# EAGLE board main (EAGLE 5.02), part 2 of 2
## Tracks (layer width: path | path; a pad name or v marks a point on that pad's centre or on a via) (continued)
GND  (via drill 0.51, 0.6, 0.7, 3.2) (continued)
  pour Bottom: 75.41,20.95 84.61,11.75 84.61,11.75 93.66,20.8 84.45,30
  pour Bottom: 54.61,67.31 54.61,54.93 55.88,53.66 63.02,53.66 64.77,51.91 64.77,31.91 32.86,0 120.02,0 120.02,67.31
  pour Top: 54.61,67.31 54.61,54.93 55.88,53.66 63.02,53.66 64.77,51.91 64.77,31.91 32.86,0 120.02,0 120.02,67.31
  pour Bottom: 0,68.42 43.02,68.42 44.13,67.31 67.79,67.31 75.72,67.31 120.02,67.31 120.02,107.95 66.99,107.79 66.99,123.98 91.28,147.95 98.74,147.95 103.19,152.4 103.19,166.85 0,166.85
  pour Top: 0,68.42 43.02,68.42 44.13,67.31 120.02,67.31 120.02,107.95 98.43,107.95 91.92,107.79 83.19,107.79 66.99,107.79 66.99,113.98 66.99,116.68 66.99,123.98 69.22,126.21 71.91,128.59 91.28,147.95 98.74,147.95 103.19,152.4 103.19,166.85 0,166.85
GND_VGA  (via drill 0.51)
  Top 0.203: v87.31,129.38 90.17,129.38 90.81,130.02 100.17,130.02 100.65,130.49 108.58,130.49 X8.8 | v88.74,127.95 91.28,127.95 92.08,128.75 100.17,128.75 100.65,128.27 X8.7 | v90.01,126.68 92.55,126.68 93.34,127.48 99.85,127.48 101.36,125.97 108.51,125.97 X8.6
  Bottom 0.203: 83.76,116.3 D3.14 | 83.76,116.3 83.82,116.36 83.82,116.84 | D3.15 83.79,116.81 83.82,116.84 | D3.12 84.04,115.51 83.88,115.51 83.76,115.63 83.76,116.3 | 90.96,119.86 89.85,119.86 | 89.85,119.86 89.69,119.86 | 89.85,119.86 89.85,120.33 | D3.39 89.88,120.36 89.85,120.33 | 84.04,121.51 D3.25 | D3.1 89.63,115.63 89.53,115.73 | 89.53,115.73 89.06,115.73 89.12,115.66 D3.2 | 88.9,135.73 | 88.9,135.73 C8.2 | 88.9,135.73 90.49,135.73 90.96,135.25 D2.7 90.96,134.14 | 90.96,119.86 D3.40 | 90.96,119.86 93.5,119.86 98.11,119.86 | D3.25 84.04,121.54 | 89.85,120.33 89.85,121.44 88.11,121.44 87.15,121.44 | 84.45,121.44 84.55,121.54 | 84.45,121.44 85.57,121.44 87.15,121.44 | 84.04,121.51 84.07,121.51 84.14,121.44 84.45,121.44 | 83.82,116.84 83.82,121.28 84.04,121.51 | 87.15,121.44 87.09,121.51 | 89.85,119.86 89.85,116.05 89.53,115.73 | 108.58,135.1 108.61,135.12 X8.10 108.58,135.1 | X8.5 107.42,136.26 108.58,135.1 | v89.85,132.71 90.49,132.71 90.96,133.19 90.96,134.14 | 90.96,134.14 | C10.2 109.67,151.89 109.7,151.92 109.86,151.76 109.86,149.38 | 100.65,123.82 R11.2 | 100.65,123.82 | 98.11,119.86 | 98.11,119.86 98.9,119.06 99.85,118.11 100.65,118.11 R12.2 101.54,118.05 102.08,118.59 102.08,123.19 102.08,123.67 | 100.65,123.67 | 100.65,123.67 R11.2 | 102.08,123.67 100.65,123.67 | 111.28,124.62 110.33,123.67 102.08,123.67 | 111.28,124.62 112.24,125.57 112.55,125.89 112.48,125.96 112.48,125.97 | 111.28,124.62 | 112.24,128.27 112.22,128.26 X8.7 102.41,128.26 102.08,128.59 102.08,129.38 R9.1 101.92,129.38 | 112.23,125.97 X8.6 102.47,125.97 102.08,126.36 102.08,127.16 | 112.23,125.97 112.24,125.97 | 102.08,127.16 | 102.08,127.16 R8.1 101.92,127.16
  Bottom 0.203: 102.5,130.54 X8.8 112.21,130.54 112.24,130.57 112.47,130.57 112.55,130.65 | D3.27 85.06,126.81 85.06,127.13 v87.31,129.38 | 101.92,131.6 | 87.09,126.3 87.07,126.21 87.09,124.76 D3.31 | 88.11,124.78 D3.33 | 101.92,127.16 | 112.48,125.97 112.39,125.89 112.31,125.97 112.23,125.97 | 112.48,125.97 | 112.55,130.65 | 112.55,135.1 | 112.55,135.1 108.58,135.1 | D3.26 84.52,122.78 84.45,122.71 84.39,122.78 D3.25 | 87.09,126.3 | 87.09,126.3 v88.74,127.95 | C11.2 98.58,124.3 99.06,123.82 | 99.06,123.82 | 99.06,123.82 99.22,123.67 100.65,123.67 | 100.65,123.67 | 100.65,123.67 R11.2 | 88.11,124.78 | v90.01,126.68 88.11,124.78 | 102.5,130.54 | 102.5,130.54 101.92,131.13 102.02,131.23 R10.1 101.92,131.6 | 101.92,131.6 | 101.92,131.6
  Bottom 0.61: L3.2 110.65,154.78 110.49,154.62 C9.- 109.86,154.62 109.86,149.38 112.55,146.68 112.55,138.11 112.55,135.1 112.55,130.65 112.55,126.05 112.48,125.97
  other vias: 74.77,126.36 78.11,129.7 80.65,132.08 83.03,134.62 78.26,124.14 84.77,120.65 84.77,118.11 87.47,120.65 89.22,117.95 87.63,116.36 100.97,135.25 117.79,123.98 117.79,130.97 117.63,138.11 117.79,117.79 100.81,139.86 106.05,139.86 111.28,139.86 111.44,122.4 113.19,152.08 116.52,152.08 113.19,149.54 116.52,149.54 108.58,149.54 117.63,144.3 114.3,117.79 114.3,123.98 114.3,130.97 114.3,138.11 114.3,144.3 80.64,127.32 83.03,130.33 70.64,119.38 70.64,112.55 101.44,113.19 107.63,113.19 113.67,113.19
  pour Bottom: 83.82,121.6 83.82,115.57 89.85,115.57 89.85,121.6
  pour Top: 104.3,155.73 120.02,156.05 120.02,108.43 101.6,108.43 100.01,108.43 92.55,108.27 87.63,108.27 84.93,108.27 84.45,108.27 83.5,108.27 81.92,108.27 80.96,108.27 80.33,108.27 78.9,108.27 78.11,108.27 77.63,108.27 67.79,108.27 67.79,123.67 69.53,125.41 91.44,147 98.9,147 104.3,152.4
  pour Bottom (isolate 0.406): 104.3,155.73 120.02,156.05 120.02,108.58 67.79,108.43 67.79,123.67 91.44,147 98.9,147 104.3,152.4
HEADPHONE_L
  Bottom 0.254: 15.08,54.77 18.41,54.77 19.53,53.66 C27.- | 15.08,54.77 15.08,54.93 | 15.08,54.93 R28.2 | 15.08,54.93 | 13.02,53.65 13.02,53.66 | X11.2 13.02,53.65 | X12.L 12.6,55.19 13.02,54.77 | 13.02,53.65 13.02,53.66 13.02,54.77 | 13.02,53.65 | 13.02,54.77 15.08,54.77
HEADPHONE_R  (via drill 0.7)
  Top 0.254: X11.1 11.75,51.12 11.75,59.37 v13.02,60.64
  Bottom 0.254: 15.08,60.64 18.1,60.64 19.53,62.07 21.43,62.07 | 21.43,62.07 | 21.43,62.07 C24.- | 15.08,60.64 R27.2 15.08,60.48 | 15.08,60.64 v13.02,60.64 12.38,60.01 10.95,60.01 10.32,59.37 10.32,55.56 9.68,54.93 9.68,53.5 9.7,53.51 X12.R
IOB  (via drill 0.51)
  Top 0.203: v89.69,130.17 90.17,130.65 100.01,130.65 100.97,131.6 106.05,131.6 X8.3
  Bottom 0.203: X8.3 | 103.74,131.69 103.66,131.69 | 103.74,131.69 104.03,131.69 | 103.66,131.69 103.59,131.69 | X8.3 | D3.28 85.57,126.05 v89.69,130.17 | 103.66,131.69 103.66,131.76 | X8.3 103.74,131.69 | X8.3 | 103.74,131.6 | 103.74,131.6 R10.2 | 103.66,131.69 103.66,131.68 103.74,131.6
IOG  (via drill 0.51)
  Top 0.203: v90.96,128.9 91.44,129.38 106.05,129.38 X8.2
  Bottom 0.203: R9.2 103.66,129.38 | R9.2 103.66,129.38 | D3.32 87.6,125.54 v90.96,128.9 | R9.2 103.66,129.38 | 103.66,129.38 103.69,129.4 | X8.2 106.05,129.38 R9.2
IOR  (via drill 0.51)
  Top 0.203: v92.23,127.63 92.55,127.95 92.71,128.11 100.01,128.11 100.97,127.16 106.05,127.16 X8.1
  Bottom 0.203: D3.34 88.61,123.86 89.38,124.62 v92.23,127.63 | X8.1 106.05,127.16 | 106.05,127.16 R8.2 | 106.05,127.16
LCD-B0  (via drill 0.51)
  Top 0.203: X1.17 79.38,76.83 84.61,81.91 84.61,104.62 | 84.61,104.62 84.58,104.65 | v81.44,111.6 81.44,110.65 84.6,107.49 X7.20 84.6,104.63 84.61,104.62
  Bottom 0.203: v81.44,111.6 81.44,116.84 81.92,117.32 D3.16
LCD-B1  (via drill 0.51)
  Top 0.203: X1.18 | X1.18 78.26,71.12 | 78.26,71.12 | 78.26,71.12 78.11,71.28 78.11,76.52 83.82,81.91 | 83.82,81.91 | 83.82,81.91 84.1,82.2 X7.19 | v80.64,112.55 80.64,110.81 84.1,107.35 X7.19 | X7.19 84.14,104.7
  Bottom 0.203: D3.17 81.15,117.82 80.64,117.32 v80.64,112.55
LCD-B2  (via drill 0.51)
  Top 0.203: X1.19 76.83,76.04 83.6,82.49 X7.18 83.6,107.22 79.85,110.97 v79.85,113.51
  Bottom 0.203: D3.18 80.39,118.33 79.85,117.79 v79.85,113.51
LCD-B3  (via drill 0.51)
  Top 0.203: X1.20 75.56,71.28 75.56,75.56 82.95,82.63 83.1,82.79 X7.17 83.1,107.08 79.06,111.12 v79.06,114.46
  Bottom 0.203: D3.19 79.63,118.84 79.06,118.27 v79.06,114.46
LCD-B4  (via drill 0.51)
  Top 0.203: 82.55,83.03 74.3,75.09 X1.21 | 82.55,83.03 82.42,82.89 | 82.55,83.03 82.6,83.08 X7.16 82.6,106.95 78.26,111.28 v78.26,115.41
  Bottom 0.203: D3.20 78.87,119.35 78.26,118.74 v78.26,115.41
LCD-B5  (via drill 0.51)
  Top 0.203: X1.22 74.14,70.17 73.03,71.28 73.03,74.61 81.92,83.19 | 81.92,83.19 81.92,83.18 | 81.92,83.19 | 81.92,83.19 82.1,83.37 X7.15 82.1,106.81 77.47,111.44 v77.47,116.36
  Bottom 0.203: v77.47,116.36 77.47,119.22 78.11,119.86 D3.21
LCD-B6  (via drill 0.51)
  Top 0.203: X1.23 71.75,74.14 81.6,83.66 X7.14 81.6,106.68 76.68,111.6 v76.68,117.32
  Bottom 0.203: D3.22 77.34,120.36 76.68,119.7 v76.68,117.32
LCD-B7  (via drill 0.51)
  Top 0.203: X1.24 70.48,71.28 70.48,73.66 80.44,83.3 | v75.88,118.27 75.88,111.76 81.1,106.54 X7.13 81.1,84 81.12,83.98 80.44,83.3 | 80.44,83.3
  Bottom 0.203: D3.23 76.58,120.87 75.88,120.17 v75.88,118.27
LCD-DVAL  (via drill 0.51)
  Top 0.203: v76.52,107.95 | v76.52,107.95 74.45,105.89 74.45,88.74 v72.55,86.84 | v72.55,86.84 | X1.25 69.22,73.34 | 69.22,73.34 | v78.9,84.77 78.9,83.66 78.9,83.34 69.22,73.66 69.22,73.34
  Bottom 0.203: D3.11 84.55,113.76 83.82,113.03 83.82,111.76 80.64,108.58 | 80.64,108.58 | 80.49,108.43 80.64,108.58 | 80.49,108.43 | 80.49,108.43 80.33,108.27 76.83,108.27 v76.52,107.95 | v78.9,84.77 74.61,84.77 v72.55,86.84 | v72.55,86.84
LCD-G0  (via drill 0.51)
  Top 0.203: X1.9 89.53,77.95 88.58,78.9 88.58,104.46 | 88.58,104.46 | v90.33,109.85 88.6,108.13 X7.28 88.6,104.63 88.58,104.62 88.58,104.46
  Bottom 0.203: v90.33,109.85 90.33,110.49 89.38,111.44 89.38,112.87 88.61,113.63 D3.3
LCD-G1  (via drill 0.51)
  Top 0.203: X1.10 88.27,71.28 88.27,78.42 88.11,78.58 88.11,104.62 | v89.22,110.33 88.1,109.21 X7.27 88.1,104.62 88.11,104.62 | 88.11,104.62 88.08,104.64
  Bottom 0.203: v89.22,110.33 88.9,110.65 88.9,112.71 88.11,113.51 D3.4
LCD-G2  (via drill 0.51)
  Top 0.203: X1.11 87,79.53 87.39,79.93 | 87.39,79.93 87.42,79.96 | 87.39,79.93 87.6,80.14 X7.26 87.6,110.46 v88.11,110.97 | v88.11,110.97
  Bottom 0.203: v88.11,110.97 88.42,111.28 88.42,112.55 87.6,113.38 D3.5
LCD-G3  (via drill 0.51)
  Top 0.203: 85.72,79.06 86.84,80.17 | 86.84,80.17 86.92,80.25 | 85.72,79.06 | 85.72,79.06 85.72,71.28 X1.12 | 86.84,80.17 87,80.33 87.1,80.43 X7.25 87.1,111.55 v87.63,112.08
  Bottom 0.203: v87.63,112.08 | v87.63,112.08 87.63,112.71 87.09,113.25 D3.6
LCD-G4  (via drill 0.51)
  Top 0.203: X1.13 84.45,78.58 86.36,80.49 | 86.36,80.49 86.44,80.57 86.42,80.59 | 86.36,80.49 86.6,80.73 X7.24 86.6,111.52 v86.04,112.08
  Bottom 0.203: D3.7 86.58,113.25 86.04,112.71 v86.04,112.08
LCD-G5  (via drill 0.51)
  Top 0.203: X1.14 83.19,71.28 83.19,78.1 86.1,81.02 X7.23 86.1,110.43 v85.57,110.97
  Bottom 0.203: v85.57,110.97 85.25,111.28 85.25,112.55 86.07,113.38 D3.8
LCD-G6  (via drill 0.51)
  Top 0.203: X1.15 81.92,77.63 85.6,81.31 X7.22 85.6,109.34 v84.45,110.33
  Bottom 0.203: D3.9 85.57,113.51 84.77,112.71 84.77,110.65 v84.45,110.33
LCD-G7  (via drill 0.51)
  Top 0.203: X1.16 80.64,71.28 80.64,77.15 85.1,81.61 X7.21 85.1,108.1 v83.34,109.85
  Bottom 0.203: D3.10 85.06,113.63 84.3,112.87 84.3,111.44 83.34,110.49 v83.34,109.85
LCD-HSYNC  (via drill 0.51)
  Top 0.203: X1.27 66.67,78.26 79.06,90.65 79.06,100.01 78.11,100.96 78.11,101.92 79.06,102.87 79.06,104.62 79.08,104.64 79.12,104.64 | v74.3,120.17 74.3,112.08 79.1,107.27 X7.9 | 79.12,104.64 X7.9 | X7.9 | 79.12,104.64 79.14,104.62
  Bottom 0.203: v74.3,120.17 74.3,120.65 74.3,121.13 75.41,122.24 81.28,122.24 83.98,124.94 83.98,127.79 87.15,130.97 94.61,130.97 96.04,132.4 96.04,133.67 | 96.04,133.67 D2.3 | 96.04,133.67
LCD-PCLK  (via drill 0.51)
  Top 0.203: v75.09,119.22 75.09,111.92 80.1,106.91 X7.11 80.1,104.63 80.08,104.6 80.08,102.54 79.3,101.76 79.3,101.04 80.09,100.25 80.08,87.54 80.08,87.38 80.01,87.31 v70.17,77.47
  Bottom 0.203: v75.09,119.22 75.09,120.65 75.82,121.38 D3.24 | R1.2 69.11,76.57 v70.17,77.47
LCD-R0  (via drill 0.51)
  Top 0.203: X1.1 99.69,74.29 92.71,81.12 | 92.71,81.12 | 92.71,81.12 92.6,81.23 X7.36 92.6,106.57 97.79,111.76 v97.79,118.27
  Bottom 0.203: 97.79,118.59 v97.79,118.27 97.79,118.74 97.19,119.35 D3.41
LCD-R1  (via drill 0.51)
  Top 0.203: X1.2 98.42,71.28 98.42,74.61 92.1,80.94 X7.35 92.1,106.71 97,111.6 v97,117.47
  Bottom 0.203: 97,117.63 97,117.79 | D3.42 96.42,118.84 97,118.27 97,117.63 | v97,117.47 97,117.63
LCD-R2  (via drill 0.51)
  Top 0.203: X1.3 97.16,75.09 91.6,80.64 91.6,80.65 X7.34 91.6,106.84 95.89,111.12 | 95.89,111.12 | 95.89,111.12 96.04,111.28 | 96.04,111.28 | 96.04,111.28 96.2,111.44 v96.2,116.36
  Bottom 0.203: D3.43 95.82,118.33 96.2,117.95 v96.2,116.36
LCD-R3  (via drill 0.51)
  Top 0.203: X1.4 95.89,71.28 95.89,75.56 91.1,80.35 X7.33 91.1,106.98 95.41,111.28 v95.41,115.41
  Bottom 0.203: D3.44 94.9,117.82 95.41,117.32 v95.41,115.41
LCD-R4  (via drill 0.51)
  Top 0.203: X1.5 94.61,76.04 90.65,80.01 | 90.65,80.01 | 90.65,80.01 90.6,80.06 X7.32 90.6,107.11 94.61,111.12 v94.61,114.46
  Bottom 0.203: D3.45 94.14,117.32 94.61,116.84 v94.61,114.46
LCD-R5  (via drill 0.51)
  Top 0.203: X1.6 93.34,71.28 93.34,76.52 90.17,79.69 | 90.17,79.69 | 90.17,79.69 90.1,79.76 X7.31 90.1,107.25 93.66,110.81 93.82,110.97 v93.82,113.51
  Bottom 0.203: D3.46 93.38,116.81 93.82,116.36 v93.82,113.51
LCD-R6  (via drill 0.51)
  Top 0.203: 89.69,79.37 92.08,76.99 X1.7 | 89.69,79.37 | 89.69,79.37 89.6,79.47 X7.30 89.6,107.38 93.03,110.81 v93.03,112.55
  Bottom 0.203: D3.47 92.46,116.3 93.03,115.73 v93.03,112.55
LCD-R7  (via drill 0.51)
  Top 0.203: X1.8 90.81,71.28 90.81,77.47 89.1,79.17 X7.29 89.1,107.52 92.23,110.65 v92.23,111.6
  Bottom 0.203: D3.48 91.69,115.79 92.23,115.25 v92.23,111.6
LCD-VSYNC  (via drill 0.51)
  Top 0.203: X1.29 64.14,76.99 78.58,91.44 78.58,99.85 77.47,100.96 77.47,101.92 78.58,103.03 78.58,104.62 | 78.58,104.62 | v73.5,121.13 73.5,112.24 78.6,107.14 X7.8 78.6,104.64 78.58,104.62
  Bottom 0.203: v73.5,121.13 73.5,121.6 74.77,122.87 81.12,122.87 83.34,125.09 83.34,128.11 87.47,132.24 87.47,136.84 87.79,137.16 90.01,137.16 91.12,138.27 94.14,138.27 94.77,138.91 94.77,140.02 | 94.77,140.02 | 94.77,140.02 D2.11
LINE_IN_L  (via drill 0.7)
  Top 0.254: X13.2 31.59,25.72 29.53,27.78 17.62,27.78 v15.56,29.84
  Bottom 0.254: R39.2 16.03,32.07 15.56,31.59 | v15.56,29.84 | 15.56,31.59 v15.56,29.84 | X15.L 15.56,31.11 15.56,31.59
LINE_IN_R  (via drill 0.7)
  Top 0.254: X13.1 33.02,24.45 33.02,26.35 30.64,28.73 21.59,28.73 v13.65,36.67
  Bottom 0.254: R34.2 14.76,37.78 13.89,36.91 | v13.65,36.67 13.89,36.91 | 13.89,36.91 13.97,36.99 13.81,36.83 v13.65,36.67 | v13.65,36.67 13.65,34.29 12.86,33.5 10.95,33.5 10,32.54 10,27.3 9.68,26.99 9.7,26.97 X15.R
LINE_OUT_L  (via drill 0.7)
  Top 0.254: X11.6 19.68,50.8 19.68,44.93 v18.1,43.34
  Bottom 0.254: 15.88,41.59 R26.2 15.93,41.69 16.03,41.59 C23.2 18.1,41.59 v18.1,43.34
  Bottom 0.305: 15.88,41.59 14.05,41.59 12.62,43.02 12.62,44.37 12.7,44.45 | 12.7,44.45 | 12.7,44.45 X10.L
LINE_OUT_R
  Bottom 0.254: 17.94,47.62 | 17.94,47.62 C16.2 18.1,47.62 X11.5 | 17.94,47.62 17.84,47.52 R25.2 15.82,47.52 15.72,47.62 12.7,47.62 | 12.7,47.62 | 12.7,47.62 11.75,46.67 10.32,46.67 9.68,46.04 9.68,40.16 9.7,40.18 X10.R
MIC1
  Bottom 0.254: C34.1 18.73,17.62 19.21,18.1 22.86,18.1 23.65,17.3 27.46,17.3 29.37,19.21 29.37,26.83 30.8,28.26 37.47,28.26 39.21,30 39.21,31.27 38.42,32.07 D7.21
MIC1_IN  (via drill 0.7)
  Top 0.254: X14.5 | X14.5 11.75,24.45 11.75,16.03 v13.02,14.76
  Bottom 0.254: X16.L 12.6,15.18 v13.02,14.76
  Bottom 0.61: X16.L 12.7,17.78 12.86,17.62 C34.2
MIC1_SUP
  Bottom 0.254: R36.1 14.13,19.68 13.65,20.16 13.02,20.16 | 13.02,20.16 11.27,20.16 10.48,19.37 10.48,16.35 9.68,15.56 9.68,13.65 9.7,13.64 X16.R | X14.6 13.02,20.16
MIC2
  Bottom 0.254: C44.1 22.6,26.88 24.61,28.89 37.31,28.89 38.58,30.16 38.58,31.11 37.91,31.78 D7.22
MIC2_IN
  Bottom 0.254: 20.95,25.72 C44.2 | X14.1 20.95,25.72 | 20.95,25.72
MIC2_SUP
  Bottom 0.254: R41.1 20.95,23.18 X14.2
N$1
  Bottom 0.203: D2.10 93.5,141.6 93.66,141.76 97.16,141.76 97.31,141.6 97.31,140.02 | 97.31,140.02 | 97.31,140.02 D2.13
N$2
  Bottom 0.203: D2.4 94.77,135.1 95.25,135.57 98.11,135.57 98.58,135.1 98.58,133.98 | 98.58,133.98 | 98.58,133.98 D2.1
N$3  (via drill 0.76)
  Top 0.203: 115.25,45.08 v115.73,45.08 115.25,45.08 | 115.25,45.08 115.09,45.08 | X21.P$8 113.02,44.43 113.67,45.08 115.25,45.08
  Bottom 0.203: v115.73,45.08 R52.2 | v115.73,45.08
N$4
  Bottom 0.203: D8.CTS 4.13,79.53 5.24,80.64 5.24,90.96 3.97,92.23 D8.RTS
N$5
  Bottom 0.203: 40.32,135.57 | R21.2 40.32,135.57 | D5.9 40.96,136.21 40.32,135.57
N$6  (via drill 0.76)
  Top 0.203: v104.14,90.8 104.14,82.23 103.82,81.91 v103.82,79.22 | v103.82,79.22
  Bottom 0.203: 112.24,82.07 D1.6 112.37,82.05 112.24,81.91 112.08,82.07 111.12,82.07 110.17,81.12 107.31,78.26 104.78,78.26 v103.82,79.22 103.82,79.37 | V3.1 109.38,89.7 108.9,90.17 107.63,90.17 107,90.8 v104.14,90.8 | 103.82,79.37 R5.1 103.82,81.12 103.66,81.28 | 103.82,79.37 v103.82,79.22
N$7
  Bottom 0.203: D3.36 89.63,123.13 89.85,123.35 91.76,123.35 92.23,123.82 96.04,123.82 96.52,124.3 96.52,125.25 C13.2
N$8
  Bottom 0.203: D3.35 89.12,123.57 89.38,123.82 90.81,123.82 91.44,123.82 92.87,125.25 94.46,125.25 | 94.46,125.25 | 94.46,125.25 C12.2
N$9
  Bottom 0.508: V3.3 108.43,95.57 108.27,95.73 108.11,95.73 | L1.P$2 106.68,95.73 108.11,95.73 | V2.A 108.13,95.75 108.11,95.73
N$10
  Bottom 0.203: 113.82,89.75 R6.1 | 113.82,89.75 113.93,89.75 | D1.3 106.19,82.06 106.2,82.07 108.11,82.07 108.27,82.23 109.22,83.18 109.22,85.41 110.33,86.52 113.82,86.52 116.2,86.52 116.68,86.99 116.68,89.53 116.52,89.69 113.82,89.69 113.82,89.75
  Bottom 0.508: 113.19,91.92 R4.2 | R6.1 113.19,91.92 | 113.19,91.92
N$11
  Bottom 0.203: D3.37 91.85,121.38 | 91.85,121.38 | 91.85,121.38 | 100.65,122.08 R11.1 | 100.65,122.08 100.65,121.76 100.65,121.6 100.17,121.13 93.34,121.13 92.71,121.76 92.23,121.76 91.85,121.38 | 100.65,122.08 100.49,121.92 | 91.85,121.38
N$12
  Bottom 0.254: D7.3 46.09,39.56 46.16,39.58 47.31,40.72 | 47.31,40.72 | 47.31,40.72 50.88,40.72 | 50.88,40.72 | 50.88,40.72 51.44,40.16 53.98,40.16 54.13,40 54.13,38.1 | 54.13,36.99 54.2,36.92 B2.2 | 57.63,38.1 | 57.63,38.1 C38.1 | B2.2 57.56,38.04 57.63,38.1 | 54.13,38.1 | 54.13,38.1 B2.2
N$13
  Bottom 0.254: D7.2 45.78,40.07 46.91,41.2 50.88,41.2 51.44,41.75 51.44,46.51 52.55,47.62 54.13,47.62 54.2,47.69 B2.1 57.4,47.69 57.57,47.52 C37.1
N$15
  Bottom 1.016: X4.2 101.12,77.79 101.12,80.96 | 101.12,80.96 | 101.12,80.96 V1.A | 101.12,80.96
N$16
  Bottom 0.254: R32.1 C32.2 43.55,28.04 43.18,28.42 R31.1
N$17
  Bottom 0.254: 40.48,25.72 C31.2 | 40.48,25.72 | 40.48,25.72 | R29.1 40.48,25.72 | R30.1 40.54,25.77 40.48,25.72
N$18
  Bottom 0.254: D7.36 33.24,40.58 31.27,42.54 31.27,43.66 29.05,45.88 25.4,45.88 23.76,47.52 C21.2 19.95,47.52 19.84,47.62 | 19.84,47.62 | C16.1 19.84,47.62
N$19
  Bottom 0.254: D7.35 31.21,40.07 29.53,41.75 29.53,42.7 28.26,43.97 25.4,43.97 23.12,41.69 C22.2 21.91,41.59 C23.1
N$20
  Bottom 0.254: D7.41 38.93,45.53 36.83,47.62 34.61,47.62 32.86,49.37 32.86,59.85 30.64,62.07 29.53,62.07 C24.+
N$21
  Bottom 0.254: C27.+ 28.73,53.66 31.59,50.8 31.59,48.74 33.97,46.35 36.2,46.35 37.78,44.77 37.91,44.58 D7.39
N$22  (via drill 0.7)
  Top 0.254: v43.02,32.23 v40.01,32.23 37.94,30.16 32.7,30.16 30.96,31.91 v30.96,34.77
  Bottom 0.254: D7.28 33.02,36.51 32.38,35.88 32.38,35.08 32.07,34.77 v30.96,34.77 | v40.01,32.23 40.48,32.23 | 40.48,32.23 40.96,32.23 40.96,33.5 | 40.96,33.5 | 40.96,33.5 D7.16 | D7.17 40.45,32.26 40.48,32.23 | D7.18 39.94,32.29 v40.01,32.23 | v40.01,32.23 39.53,32.23 39.43,32.29 D7.19 | D7.20 38.93,32.26 v40.01,32.23 | D7.13 42.48,32.77 v43.02,32.23 44.61,33.81 44.61,34.92 44.55,34.99 D7.12
N$23
  Bottom 0.254: D7.15 41.47,31.62 40.96,31.11 | 40.96,31.11 | 40.96,31.11 40.48,30.64 40.48,29.69 | 40.48,29.69 | C31.1 40.48,29.69
N$24
  Bottom 0.254: C28.1 31.11,57.78 32.23,56.67 32.23,49.05 34.29,46.99 36.51,46.99 38.42,45.08 D7.40
N$25
  Bottom 0.254: D7.14 41.97,31.69 42.55,31.11 44.61,31.11 45.24,30.48 45.24,29.84 45.35,29.74 | 45.35,29.74 45.4,29.69 | C32.1 45.35,29.74
N$26
  Bottom 0.254: R40.1 27.78,25.24 27.62,25.08 27.15,25.08 25.24,23.18 C45.+ 25.24,23.02 | 25.24,23.02 | R41.2 25.08,23.18 25.24,23.02
N$27
  Bottom 0.254: 22.7,32.07 C35.2 | 20.48,32.07 22.7,32.07 | R39.1 20.48,32.07 | 22.7,32.07 | 20.48,32.07 | 20.48,32.07 R38.1 | 20.48,32.07
N$28
  Bottom 0.254: 18.26,37.78 R34.1 20.48,37.78 | 20.48,37.78 C33.2 | 20.48,37.78 R37.1
N$29
  Bottom 0.254: R36.2 20.95,19.68 C36.+ 23.77,19.72 23.81,19.68 R35.1
N$30
  Bottom 0.254: 24.29,37.78 C33.1 24.92,37.78 25.72,36.99 25.72,31.59 27.15,30.16 36.99,30.16 37.31,30.48 37.31,30.8 36.89,31.21 D7.24
N$31
  Bottom 0.254: C35.1 24.61,32.07 24.61,31.75 26.83,29.53 37.15,29.53 37.78,30.16 37.78,31.11 37.4,31.5 D7.23
N$32
  Bottom 0.254: C40.1 29.79,33.08 29.84,33.02 C41.1 31.69,33.08 31.75,33.02 31.81,33.08 C39.1 32.6,33.08 33.02,33.5 33.02,35.56 33.46,36 D7.27
N$33
  Bottom 0.254: D7.30 32.48,37.53 31.59,38.42 31.11,38.42 C42.2
N$34
  Bottom 0.254: D7.29 32.42,37.02 31.75,36.35 C43.2 30.96,36.35
N$35  (via drill 0.7)
  Top 0.254: v63.02,50.16 v58.26,50.16
  Bottom 0.203: 13.34,8.57 13.18,8.57 11.91,7.3 10.32,7.3 9.53,6.51 9.53,5.24 11.07,3.69 | 11.07,3.69 11.11,3.65 | B1.3 11.07,3.69
  Bottom 0.254: D7.48 42.48,42.48 43.5,43.5 | 43.5,43.5 | 43.5,43.5 50.64,50.64 57.78,50.64 v58.26,50.16 | 63.02,50.01 v63.02,50.16 | 63.02,50.01 | 63.02,50.01 62.55,49.53 62.55,34.29 62.55,33.81 59.05,30.32 58.74,30.32 48.58,30.32 47.94,29.69 47.94,22.7 45.09,19.84 34.45,19.84 23.18,8.57 13.34,8.57
N$36  (via drill 0.76)
  Top 0.203: 115.25,34.92 v115.73,34.92 115.25,34.92 | X21.P$12 109.27,40.43 110.17,39.53 114.78,34.92 115.25,34.92
  Bottom 0.203: v115.73,34.92 R46.2 | v115.73,34.92
N$37  (via drill 0.76)
  Top 0.203: v115.73,37.46 115.09,37.46 114.78,37.46 110.81,41.43 X21.P$11
  Bottom 0.203: v115.73,37.46 R47.2 | v115.73,37.46
N$38  (via drill 0.76)
  Top 0.203: v115.73,40 115.09,40 114.78,40 112.35,42.43 X21.P$10
  Bottom 0.203: v115.73,40 R49.2 | v115.73,40
N$39  (via drill 0.76)
  Top 0.203: v115.73,50.16 115.09,50.16 114.94,50.16 111.2,46.43 X21.P$6
  Bottom 0.203: v115.73,50.16 R50.2 | v115.73,50.16
N$40
  Bottom 0.203: D10.31 95.27,42.68 99.54,38.42 99.54,36.35 100.81,35.08 106.05,35.08 106.52,35.56 106.52,36.35 106.39,36.38 | 106.39,36.38 106.52,36.51 | 106.39,36.38 C52.1
N$41
  Bottom 0.203: D10.28 96.77,43.09 99.22,40.64 | 99.22,40.64 | 99.22,40.64 99.54,40.32 106.2,40.32 106.52,40 106.52,39.21 106.52,39.37 C52.2 106.52,38.34 106.84,38.02 110.25,38.02 110.81,37.46 R47.1
N$42
  Bottom 0.203: D10.30 95.77,42.82 100.01,38.58 100.01,37.15 100.81,36.35 103.82,36.35 103.85,36.38 C51.1
N$43
  Bottom 0.203: 96.36,42.86 96.28,42.94 | 96.36,42.86 100.04,39.18 C51.2 104.3,38.02 104.78,37.54 109.78,37.54 110.33,36.99 110.33,35.48 110.89,34.92 R46.1 | D10.29 96.27,42.95 96.36,42.86
N$44
  Bottom 0.203: D10.32 94.77,42.55 99.06,38.26 99.06,36.19 100.65,34.61 107.95,34.61 108.74,35.4 108.74,36.19 C53.1
N$45
  Bottom 0.203: D10.27 97.27,43.22 99.69,40.8 107.95,40.8 108.74,40 | 108.74,40 R49.1 | C53.2 108.74,40
N$46
  Bottom 0.203: D10.17 99.86,48.26 101.28,49.69 103.98,49.69 104.11,49.82 C54.1
N$47
  Bottom 0.203: D10.18 102.25,47.76 103.03,46.99 104.14,46.99 | 104.14,46.99 | 104.14,46.99 C54.2 104.3,48.26 104.69,48.66 109.78,48.66 111.28,50.16 111.92,50.16 | 111.92,50.16 | 111.92,50.16 R50.1
N$48
  Bottom 0.203: D10.16 98.27,49.37 99.85,50.96 106.05,50.96 106.52,50.48 106.52,49.85 106.36,49.85 C56.1
N$49
  Bottom 0.203: D10.19 101.48,47.26 103.03,45.72 105.89,45.72 106.52,46.35 | 106.36,46.83 | 106.36,46.83 C56.2 | 106.52,46.35 106.36,46.83 | 106.52,46.35 106.52,47.78 106.92,48.18 109.78,48.18 110.49,47.47 111.6,47.47 111.76,47.62 R51.1
N$50
  Bottom 0.203: D10.15 97.77,49.51 99.69,51.43 | 99.69,51.43 99.54,51.28 99.69,51.43 | 99.69,51.43 108.27,51.43 108.74,50.96 C57.1
N$51
  Bottom 0.203: D10.20 101.19,46.76 101.92,46.04 102.71,45.24 108.74,45.24 | 108.74,45.24 108.74,46.35 C57.2 | R52.1 111.92,45.08 111.76,45.24 108.74,45.24
N$52
  Bottom 0.203: D10.14 97.27,49.64 100.33,52.7 105.73,52.7 | 105.73,52.7 | 105.73,52.7 C58.1
N$53
  Bottom 0.203: D10.13 96.77,49.78 100.97,53.97 108.27,53.97 108.74,53.5 108.74,52.7 C58.2 112.24,52.7 | 112.24,52.7 R53.1 | 112.24,52.7
N$54
  Bottom 0.203: D10.9 94.77,50.32 100.33,55.88 100.33,57.94 101.28,58.9 103.98,58.9 | 103.98,58.9 | 103.98,58.9 C59.1
N$55
  Bottom 0.203: D10.10 95.27,50.18 101.12,56.04 103.82,56.04 103.85,56.07 C59.2 104.3,57.31 104.7,57.71 109.86,57.71 110.41,58.26 110.41,59.69 111.05,60.32 111.68,60.32 111.76,60.25 111.84,60.32 R56.1
N$56
  Bottom 0.203: D10.8 93.66,48.26 93.34,48.58 93.34,49.53 99.85,56.04 99.85,59.37 100.81,60.32 106.05,60.32 106.52,59.85 106.52,58.9 C60.1
N$57
  Bottom 0.203: D10.11 95.77,49.96 95.89,50.16 100.65,54.93 106.05,54.93 106.52,55.4 C60.2 106.52,56.83 106.92,57.23 110.57,57.23 111.12,57.78 R57.1
N$58
  Bottom 0.203: D10.7 93.52,47.76 92.87,48.42 92.87,49.69 99.38,56.2 99.38,59.53 100.65,60.8 107.95,60.8 108.74,60.17 108.74,58.9 108.58,58.9 C61.1
N$59
  Bottom 0.203: D10.12 96.27,49.91 100.81,54.45 107.79,54.45 108.74,55.24 108.74,56.04 | 108.74,56.04 | 108.74,56.04 C61.2 110.14,56.07 110.97,55.24 R58.1
N$60
  Bottom 0.203: R48.2 91.12,43.82 91.12,43.81 | D10.1 93.02,44.76 92.08,43.81 91.12,43.81 | 91.12,43.81 | 91.12,43.81 C55.1
N$61
  Bottom 0.203: D10.4 93.44,46.26 92.87,46.83 91.92,47.78 91.92,49.21 91.44,49.69 R45.2 | R48.1 87.63,48.58 88.74,49.69 R45.2 | R45.2 | R45.2 | R45.2
N$62  (via drill 0.76)
  Top 0.203: v115.73,47.62 115.09,47.62 114.46,47.62 112.27,45.43 X21.P$7
  Bottom 0.203: v115.73,47.62 R51.2 | v115.73,47.62
N$63
  Bottom 0.203: R20.2 32.07,151.13 32.07,150.18 D5.1 32.07,148.27
N$64  (via drill 0.76)
  Top 0.203: v115.73,52.7 114.94,52.7 114.78,52.7 113.82,51.75 113.82,50.48 110.78,47.43 X21.P$5
  Bottom 0.203: v115.73,52.7 R53.2 | v115.73,52.7
N$65  (via drill 0.76)
  Top 0.203: v115.73,60.32 112.08,60.32 110.97,59.21 110.97,59.05 110.97,51.75 109.65,50.43 X21.P$2
  Bottom 0.203: 113.67,60.32 | 113.67,60.32 R56.2 v115.73,60.32 | v115.73,60.32
N$66  (via drill 0.76)
  Top 0.203: v115.73,57.78 115.09,57.78 113.51,57.78 | 113.51,57.78 113.82,57.78 | X21.P$3 110.24,49.43 111.92,51.12 111.92,51.28 | 113.51,57.78 111.92,56.2 111.92,51.28 | 111.92,51.28 | 111.92,51.28
  Bottom 0.203: R57.2 113.51,57.78 v115.73,57.78 | v115.73,57.78
N$67  (via drill 0.76)
  Top 0.203: v115.73,55.24 114.94,55.24 114.78,55.24 113.82,55.24 113.03,54.45 113.03,50.8 110.67,48.43 X21.P$4
  Bottom 0.203: v115.73,55.24 R58.2 | v115.73,55.24
N$68
  Bottom 0.203: R18.2 52.55,135.57 53.18,136.21 53.18,138.43 53.34,138.59 53.32,138.61 D4.9
N$69
  Bottom 0.203: R17.2 44.45,151.13 44.29,150.97 D4.1
N$70
  Bottom 0.203: D6.P$2 17.19,151.08 15.24,153.03 15.24,155.26 17.46,157.48 26.67,157.48 27.46,156.69 27.46,156.37 R22.1
N$71
  Bottom 0.203: D6.P$5 16.8,149.88 13.81,152.88 13.81,156.37 16.51,159.07 30.48,159.07 32.54,157 R24.1
N$72
  Bottom 0.203: D6.P$3 16.8,150.68 14.45,153.03 14.45,155.73 16.99,158.27 28.73,158.27 30,157 R23.1
N$73
  Bottom 0.203: D1.1 107.63,79.53 110.49,82.39 110.49,83.82 111.44,84.77 113.51,84.77 115.73,82.55 116.36,81.91 X6.2 | X6.2
N$75
  Bottom 0.203: X1.28 67.94,71.28 67.94,74.77 | 67.94,74.77 | 67.94,74.77 R1.1
SD_CD
  Bottom 0.203: X9.CD 9.8,99.42 9.84,99.38 9.84,97.63 | 9.84,97.63 9.84,97.47 12.06,95.25 38.89,95.25 43.5,99.85 43.5,115.09 49.69,121.28 49.69,127 70.48,147.8 70.48,154.62 70.96,155.1 71.28,155.1 71.75,155.57 X3.23 | 9.84,97.63 R14.2 | X3.23
SDIO-CLK  (via drill 0.51)
  Top 0.203: X2.32 61.59,161.29 61.59,160.18 60.96,159.54 60.33,158.91 60.33,152.56 59.53,151.76 56.83,151.76 v30,151.76 28.89,150.65 16.99,150.65 13.34,154.3 P1.PP | P1.PP
  Bottom 0.203: D6.P$32 26.97,144.28 28.73,146.05 28.73,150.49 v30,151.76
SDIO-CMD1  (via drill 0.51, 0.6)
  Top 0.203: X2.30 62.87,160.18 62.87,151.13 61.28,149.54 39.55,149.54 | P2.PP 7.62,153.67 8.73,152.56 13.34,152.56 14.29,151.61 14.29,150.34 15.08,149.54 16.35,149.54 | 16.35,149.54 39.55,149.54 | 16.35,149.54 v16.35,149.22 | 39.55,149.54 39.55,150.63 v39.53,150.65 | v39.53,152.64 v39.53,154.46
  Bottom 0.203: D6.P$9 17.29,148.28 v16.35,149.22 | v39.53,150.65 v39.53,152.64 | v39.53,154.46 35.56,154.46 35.4,154.62 R59.2 35.4,154.78
SDIO-D4  (via drill 0.6)
  Top 0.203: 92.08,153.19 X3.8 92.08,153.19 | v16.35,145.41 16.99,146.05 84.93,146.05 92.08,153.19 | P3.PP 8.89,151.13 9.68,150.34 9.68,146.21 10.48,145.41 v16.35,145.41 | v16.35,145.41
  Bottom 0.203: D6.P$25 16.86,141.88 16.55,141.88 16.19,142.24 16.19,145.26 v16.35,145.41
SDIO-D5  (via drill 0.51)
  Top 0.203: 93.34,155.1 93.34,153.19 85.25,145.1 v25.4,145.1 24.29,143.99 9.68,143.99 7.46,146.21 P4.PP
  Top 0.254: X3.7 | 93.34,155.1 X3.7
  Bottom 0.203: 25.39,145.08 D6.P$34 | v25.4,145.1 | 25.39,145.08 | v25.4,145.1 25.39,145.08
SDIO-D6  (via drill 0.51)
  Top 0.203: v16.35,147.95 13.81,147.95 13.18,148.59 13.18,150.49 12.54,151.13 P5.PP | P5.PP | X3.10 | X3.10 89.53,153.19 84.3,147.95 v16.35,147.95 | v16.35,147.95
  Top 0.254: X3.10 | X3.10
  Bottom 0.203: D6.P$10 16.42,147.88 v16.35,147.95
SDIO-D7  (via drill 0.51)
  Top 0.203: P6.PP 11.75,148.11 P6.PP | 90.81,155.1 90.81,153.19 84.61,147 v27.15,147 12.7,147 P6.PP | P6.PP | P6.PP
  Top 0.254: X3.9 | 90.81,155.1 X3.9
  Bottom 0.203: v27.15,147 25.08,147 23.57,145.48 D6.P$35
SDIO/!SPI!  (via drill 0.51)
  Top 0.203: X2.31 60.33,162.72 60.33,160.02 59.21,158.91 55.24,158.91 54.13,157.8 v54.13,153.83
  Bottom 0.203: D6.P$49 24.09,151.08 26.67,153.51 53.82,153.51 v54.13,153.83
SPI0-CS1  (via drill 0.51)
  Top 0.203: P14.PP 16.03,140.33 20.8,135.57 54.93,135.57 | v70.48,135.57 55.24,135.57 54.93,135.57 | v54.93,137.48 54.93,135.57
  Bottom 0.203: D4.7 51.91,146.68 52.7,145.89 58.26,145.89 59.05,145.1 59.05,142.24 | 59.05,142.24 59.05,141.6 v54.93,137.48 | R16.2 59,142.5 59.05,142.24 | X2.7 90.81,162.72 89.06,162.72 88.27,161.92 88.27,155.73 88.27,152.56 71.28,135.57 v70.48,135.57
SPI0-CS2  (via drill 0.51)
  Top 0.203: v41.59,134.46 v69.37,134.46 | v41.59,134.46 41.75,134.46 | v41.59,134.46 v29.37,134.46 21.11,134.46 16.67,138.91 9.05,138.91 P15.PP | P15.PP
  Bottom 0.203: X2.8 90.81,160.18 90.81,153.19 90.01,152.4 89.06,152.4 71.12,134.46 70.17,134.46 v69.37,134.46 | D5.7 39.69,142.24 41.91,140.02 41.91,134.78 v41.59,134.46 | v29.37,134.46 R19.2 | v29.37,134.46
SPI0-MISO  (via drill 0.51)
  Top 0.203: v67.31,132.24 v42.55,132.24 21.75,132.24 18.57,135.41 9.37,135.41 P17.PP | P17.PP
  Bottom 0.203: X2.3 95.89,162.72 95.89,153.19 93.82,151.13 | 93.82,151.13 | 93.82,151.13 89.69,151.13 70.8,132.24 v67.31,132.24 | v42.55,132.24 42.55,140.33 40.96,141.92 D5.8 40.96,151.29 42.23,152.56 52.39,152.56 53.18,151.76 D4.8 | 93.82,151.13
SPI0-MOSI  (via drill 0.51)
  Top 0.203: 33.5,131.13 29.53,131.13 | 44.93,131.13 33.5,131.13 | v66.2,131.13 44.93,131.13 | 33.5,131.13 | 33.5,131.13 v33.34,131.13 | 44.93,131.13 | 44.93,131.13 v45.56,131.13 | P16.PP 19.21,133.98 22.07,131.13 29.53,131.13 | 29.53,131.13
  Bottom 0.203: X2.4 | X2.4 98.27,160.34 | 98.27,160.34 | 98.27,160.34 98.42,160.18 98.42,160.02 98.42,153.19 95.73,150.49 | 95.73,150.49 | 95.73,150.49 95.41,150.49 90.01,150.49 70.64,131.13 v66.2,131.13 | v33.34,131.13 D5.15 | v45.56,131.13 D4.15
SPI0-SCK  (via drill 0.51)
  Top 0.203: 32.23,133.35 29.53,133.35 | 43.66,133.35 32.23,133.35 | v68.42,133.35 43.66,133.35 | 32.23,133.35 | 32.23,133.35 v32.07,133.35 | 43.66,133.35 | 43.66,133.35 v44.29,133.35 | P13.PP 17.62,137.16 21.43,133.35 29.53,133.35 | 29.53,133.35
  Bottom 0.203: X2.5 93.34,162.72 93.34,153.35 93.34,153.19 91.92,151.76 89.38,151.76 70.96,133.35 70.01,133.35 v68.42,133.35 | v32.07,133.35 D5.16 | v44.29,133.35 D4.16
SPI1-CS0
  Bottom 0.203: X9.1 29.85,119.54 29.84,119.54 33.97,119.54 | R15.2 34.08,119.64 33.97,119.54 | X2.26 67.79,160.02 64.93,160.02 62.87,157.96 62.87,155.89 62.07,155.1 60.96,155.1 60.33,154.46 60.33,140.81 39.05,119.54 33.97,119.54
SPI1-MISO
  Bottom 0.203: X2.24 71.75,160.5 70.48,159.23 70.48,155.73 69.85,155.1 68.42,155.1 67.94,154.62 67.94,146.05 49.21,127.32 49.21,121.76 32.07,104.62 30,104.62 29.85,104.77 | 29.85,104.77 29.84,104.77 | X9.7 29.85,104.77
SPI1-MOSI
  Bottom 0.203: X9.2 37.4,117.09 62.87,142.56 62.87,154.3 63.66,155.1 64.61,155.1 65.41,155.89 65.41,157.32 67.15,159.07 68.9,159.07 70.48,160.65 70.48,162.72 X2.25
SPI1-SCK  (via drill 0.51)
  Top 0.203: v39.37,117 v39.37,121.28
  Bottom 0.203: X2.29 63.98,163.99 62.87,162.88 62.87,160.18 60.33,157.64 60.33,155.73 59.69,155.1 58.74,155.1 57.78,154.15 57.78,147.95 59.69,146.05 59.69,140.97 47.78,129.06 | X9.5 31.96,109.59 v39.37,117 | 47.78,129.06 | v39.37,121.28 40.01,121.28 47.78,129.06
VCC  (via drill 0.51, 0.76)
  Top 0.508: v43.81,71.6 44.13,71.91
  Top 0.61: 61.44,77.15 49.37,77.15 44.13,71.91 v43.81,71.6 | 61.44,77.15 61.28,77.15 | 61.44,77.15 v70.01,85.72
  Bottom 0.508: V1.C 90.28,80.9 | N2.1 41.97,57.21 45.56,60.8 45.56,63.5 | 45.56,63.5 | 45.56,63.5 C17.+ 45.68,63.62 45.72,63.66 45.91,63.85 C18.1 45.91,69.5 v43.81,71.6
  Bottom 0.61: V1.C 90.65,80.96 74.93,80.96 70.17,85.72 v70.01,85.72
  Bottom 1.016: L1.P$1 95.64,95.8 95.73,95.88 94.46,94.61 94.46,88.9 | 94.46,88.9 C1.+ | 94.46,88.9 | 94.46,88.9 94.46,81.44 94.14,81.12 93.98,81.12 93.82,80.96 | 93.82,80.96 | V1.C 93.82,80.96 | 90.65,80.96 90.65,81.12 90.62,81.15 C4.1 90.62,84.58 90.96,84.93 91,84.97 C3.+ 91,85.21 90.81,85.41 91.81,86.42 N1.1
VGA-HSYNC
  Bottom 0.203: X8.13 111.12,131.6 107.95,131.6 106.68,132.87 105.41,132.87 101.28,132.87 99.54,131.13 98.58,131.13 97.31,132.4 97.31,133.83 D2.2
VGA-VSYNC
  Bottom 0.203: 103.98,135.25 101.28,137.95 96.68,137.95 96.04,138.59 96.04,139.7 | 103.98,135.25 | 103.98,135.25 104.14,135.1 106.84,135.1 107.95,133.98 111.12,133.98 X8.14 | 96.04,139.7 | 96.04,139.7 D2.12 | 96.04,139.7
VLED+  (via drill 0.76)
  Top 0.203: X5.1 103.59,103.2 103.58,103.19
  Top 0.305: v112.87,97.31 112.87,99.85 110.65,102.08 110.49,102.08 104.46,102.08 103.58,102.95 103.58,103.19
  Bottom 0.508: C2.1 111.12,91.92 111.12,92.71 V2.C 111.12,93.34 111.5,93.72 R4.1 113.19,93.82 112.87,94.14 v112.87,97.31
VLED-  (via drill 0.76)
  Top 0.203: X5.4 102.09,103.21 102.08,103.19
  Top 0.305: 102.08,103.19 102.08,102.23 102.87,101.44 109.7,101.44 111.44,99.69 111.44,96.68 112.87,95.25 113.67,95.25 v115.41,93.19
  Bottom 0.203: D1.2 107.78,80.79 109.7,82.71 109.7,85.09 110.65,86.04 113.98,86.04 116.68,86.04 117.32,86.68 117.32,90.49 116.52,91.28 R7.1
  Bottom 0.508: R7.1 115.41,91.28 v115.41,93.19
WAKE  (via drill 0.51, 0.6)
  Top 0.203: v61.91,102.08 61.91,104.46 60.01,106.36 v56.2,106.36 | v82.07,48.58 83.82,48.58 85.25,47.15 85.25,42.86 87.31,40.8 v88.42,40.8 | X3.27 66.67,157.32 67.47,158.11 82.23,158.11 83.19,157.16 83.19,152.4 83.19,151.13 v83.19,150.97
  Bottom 0.203: D9.19 87.63,30 87.63,30.48 86.84,31.27 | 86.84,31.27 | 86.84,31.27 86.52,31.59 84.14,31.59 83.66,32.07 83.66,34.61 88.42,39.37 v88.42,40.8 | v83.19,150.97 83.19,149.54 56.2,122.55 v56.2,106.36 | 64.77,74.29 65.41,73.66 65.41,63.98 80.64,48.58 v82.07,48.58 | 64.77,74.29 | 64.77,74.29 64.14,74.93 64.14,89.38 61.91,91.6 v61.91,102.08 | v61.91,102.08
XTAL1
  Bottom 0.203: D9.24 93.5,30.32 95.25,30.32 98.16,27.41 | 98.16,27.41 B3.1 | C48.2 100.49,30.16 98.16,27.83 98.16,27.41
XTAL2
  Bottom 0.203: D9.23 89.28,27.21 93.03,30.96 93.03,32.54 91.33,34.24 | 91.33,34.24 91.28,34.29 | 91.33,34.24 B3.2 | C49.2 94.17,36.39 92.02,34.24 91.33,34.24

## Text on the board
tPlace: Top | SDIO-TESTPOINTS | SPI-TESTPOINTS | RS232-TESTPOINTS | Media | X | Version 3.33 Final 01.09 | Bernhard Wörndl-Aichriedler (BWA) | www.berniwa.com
bPlace: Bottom
tNames: Media | X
